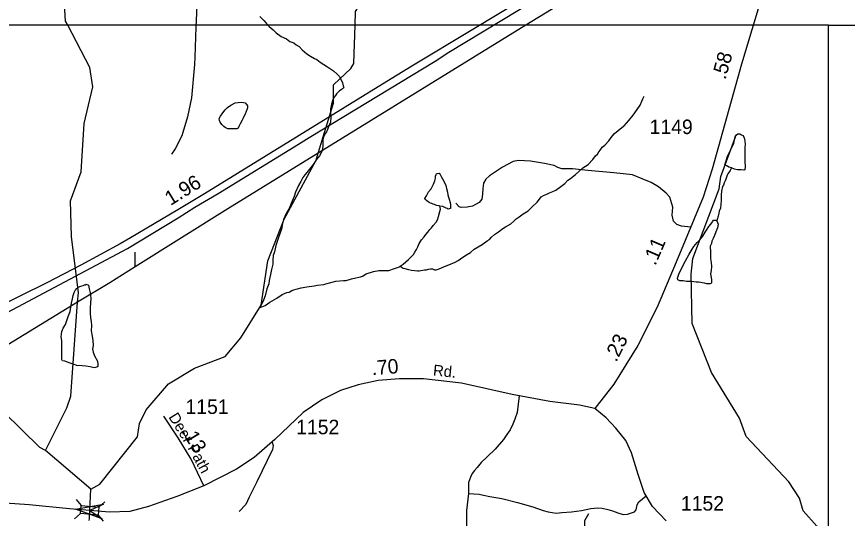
# Model space of a CAD drawing. Extents: x 2001466 to 2224147, y 644118 to 847247.
# Drawn here: x 2022908 to 2030071, y 697641 to 701966 of the extents above; entities that cross this region are included whole.
import ezdxf

# ---------------------------------------------------------------- set-up
doc = ezdxf.new("R2010")
doc.units = 0
for name, color, linetype in [('Exist Hydrographic Creek Single Shore', 7, 'Continuous'), ('Exist Hydrographic Misc Water Feature', 7, 'Continuous'), ('Exist Road Non-System Type 51', 7, 'Continuous'), ('Exist Road Primary US Divided Attributed', 7, 'Continuous'), ('Exist Road Primary US Mileage Hundredths English Label', 7, 'Continuous'), ('Exist Road Secondary Mileage Hundredths English Label', 7, 'Continuous'), ('Exist Road Secondary Structure Standard Bridge Attributed CELL', 7, 'Continuous'), ('Exist Road Secondary Structure Standard Bridge CELL', 7, 'Continuous'), ('Exist Road Secondary Type 41 Attributed', 7, 'Continuous'), ('Exist Road Secondary Type 51 Attributed', 7, 'Continuous'), ('Exist Road Secondary Type 51 Label', 7, 'Continuous'), ('Exist Road Secondary Type 51 Number Label', 7, 'Continuous'), ('Exist Utilities Electrical Transmission Line', 7, 'Continuous'), ('Map Preparation Inset Cut Line', 7, 'Continuous')]:
    doc.layers.add(name, color=color, linetype=linetype)

msp = doc.modelspace()

# ---------------------------------------------------------------- linework, layer by layer
at = {"layer": 'Exist Hydrographic Creek Single Shore'}
msp.add_line((2023549.5, 697893.6), (2023158.5, 698226.4), dxfattribs=at)
for points in [[(2023349.4, 701890.9), (2023330.5, 701927.2), (2023314.5, 702176.9), (2023438.6, 702450), (2023547.7, 702861.2), (2023547.5, 703140.7)], [(2025826.2, 701890.9), (2025830.5, 702010.9), (2025930.6, 702169.6), (2026196.5, 702820.4), (2026202.7, 702966.8)], [(2023434.6, 699504), (2023440.6, 699585.6), (2023382.6, 700069.1), (2023373.6, 700377.7), (2023465.6, 700628.4), (2023489.6, 701044.6), (2023564.5, 701361.4), (2023539.7, 701525.9), (2023349.4, 701890.9)], [(2025789.5, 701519.6), (2025814.5, 701561.7), (2025826.2, 701890.9)], [(2025507.8, 700788.4), (2025639.6, 701220.7), (2025639.6, 701378.2), (2025789.5, 701519.6)], [(2023549.5, 697893.6), (2023624.6, 697934.7), (2023949.6, 698344.8), (2023966.6, 698459.3), (2024024.4, 698576.3), (2024216.5, 698802), (2024440.5, 698935.3), (2024707.4, 699034.9), (2024840.5, 699196.1), (2025015.4, 699478), (2025073.5, 699860.8), (2025214.5, 700218.8), (2025489.5, 700728.4), (2025507.8, 700788.4)], [(2023158.5, 698226.4), (2023341.6, 698593.4), (2023374.6, 698694.5), (2023434.6, 699504)], [(2023534.5, 697623.5), (2023537.4, 697641.1), (2023538.9, 697709.3), (2023549.5, 697893.6)]]:
    msp.add_lwpolyline(points, dxfattribs=at)
at = {"layer": 'Exist Hydrographic Misc Water Feature'}
for points in [[(2025005.2, 701967.4), (2025041.1, 701933.4), (2025061.2, 701909.4), (2025087, 701881.4), (2025121, 701851.5), (2025145, 701825.5), (2025189.1, 701793.5), (2025235.2, 701773.5), (2025265.2, 701751.5), (2025297.2, 701739.5), (2025319.1, 701721.6), (2025343.1, 701707.6), (2025369.1, 701679.6), (2025409.1, 701645.7), (2025441.1, 701625.7), (2025477.2, 701605.7), (2025495.3, 701595.8), (2025525.2, 701573.7), (2025587.3, 701531.8), (2025641.2, 701499.8), (2025675.3, 701465.9), (2025689.2, 701451.9), (2025707.3, 701421.9), (2025717.3, 701395.9), (2025723.3, 701369.9), (2025725.3, 701359.8), (2025729.2, 701355.9)], [(2025705.2, 701335.8), (2025693.3, 701325.6), (2025677.3, 701311.9), (2025667.5, 701299.9), (2025657.4, 701285.9), (2025643.5, 701267.9), (2025633.5, 701247.9), (2025623.4, 701211.8), (2025615.4, 701171.9), (2025615.4, 701133.9), (2025617.5, 701097.8), (2025613.6, 701055.8), (2025601.5, 701029.9), (2025587.5, 700991.9), (2025579.5, 700971.9), (2025571.5, 700961.8), (2025557.6, 700935.8), (2025549.6, 700905.9), (2025547.7, 700879.9), (2025547.7, 700847.9), (2025541.6, 700807.8), (2025519.7, 700765.9), (2025491.8, 700729.9), (2025473.7, 700701.8), (2025443.8, 700663.8), (2025411.8, 700621.8), (2025393.8, 700601.8), (2025375.7, 700579.8), (2025359.7, 700543.8), (2025338, 700509.8), (2025311.9, 700453.7), (2025299.8, 700415.8), (2025275.8, 700353.8), (2025258, 700311.7), (2025232, 700267.7), (2025208, 700217.7), (2025200, 700181.7), (2025192.2, 700133.7), (2025170.2, 700069.7), (2025144.2, 699993.7), (2025132.3, 699937.7), (2025120.2, 699907.7), (2025116.3, 699863.7), (2025118.4, 699831.7), (2025106.3, 699785.7), (2025096.4, 699743.7), (2025086.4, 699691.7), (2025082.5, 699661.7), (2025066.5, 699619.7), (2025050.5, 699557.7), (2025036.6, 699521.7), (2025016.5, 699479.7), (2025004.6, 699457.7)], [(2025729.2, 701355.9), (2025725.3, 701349.8), (2025717.3, 701343.8), (2025711.4, 701339.9), (2025705.2, 701335.8)], [(2026214.2, 699814.4), (2026240.2, 699796.4), (2026256.2, 699794.4), (2026288.2, 699786.4), (2026312.2, 699780.5), (2026342.1, 699776.5), (2026364.1, 699774.5), (2026380.1, 699774.5), (2026426.2, 699784.6), (2026442.2, 699784.6), (2026458.2, 699788.6), (2026476.2, 699790.6), (2026494.1, 699790.6), (2026512.1, 699784.6), (2026524.2, 699784.6), (2026552.1, 699792.6), (2026570.1, 699800.6), (2026584.1, 699806.6), (2026634.1, 699826.7), (2026690.1, 699848.7), (2026715.9, 699862.7), (2026754.1, 699892.7), (2026788.1, 699912.7), (2026820.1, 699932.8), (2026852.1, 699960.8), (2026921.8, 700002.8), (2026963.8, 700032.8), (2026983.9, 700044.8), (2027003.8, 700064.8), (2027027.8, 700086.9), (2027061.8, 700110.9), (2027099.8, 700139), (2027123.8, 700153), (2027167.9, 700178.9), (2027193.7, 700202.9), (2027213.8, 700222.9), (2027239.8, 700239), (2027275.7, 700265), (2027317.5, 700293), (2027353.6, 700325), (2027395.7, 700365.1), (2027415.6, 700393.1), (2027431.6, 700413.1), (2027451.7, 700425.1), (2027479.7, 700435.1), (2027501.7, 700447.2), (2027531.6, 700457.1), (2027557.5, 700471.1), (2027599.5, 700501.1), (2027635.6, 700527.2), (2027661.4, 700555.2), (2027683.6, 700571.2), (2027727.4, 700605.2), (2027783.4, 700657.3), (2027789.4, 700663.3), (2027835.3, 700691.3), (2027875.5, 700733.3), (2027899.5, 700765.3), (2027915.5, 700779.3), (2027929.2, 700801.3), (2027943.4, 700817.3), (2027957.3, 700839.3), (2027979.3, 700857.4), (2028015.3, 700895.3), (2028033.2, 700923.4), (2028045.3, 700939.4), (2028063.1, 700957.4), (2028093.1, 700983.4), (2028141.2, 701021.4), (2028145.1, 701023.4), (2028185.1, 701071.5), (2028223.1, 701115.5), (2028257.1, 701165.4), (2028282.9, 701201.5), (2028299.1, 701237.5), (2028307.1, 701257.5), (2028315.1, 701275.5), (2028319, 701279.5)], [(2024851.6, 701073.4), (2024835.6, 701041.3), (2024823.7, 701019.3), (2024817.8, 701005.4), (2024807.7, 700999.4), (2024793.8, 700997.4), (2024767.7, 700997.4), (2024751.7, 700997.4), (2024729.6, 700997.4), (2024705.6, 701009.3), (2024693.7, 701019.3), (2024677.7, 701035.3), (2024663.8, 701055.3), (2024657.6, 701071.3), (2024655.8, 701087.3), (2024665.6, 701107.3), (2024685.5, 701137.3), (2024705.6, 701161.3), (2024717.5, 701173.3), (2024725.5, 701183.3), (2024755.6, 701203.3), (2024793.6, 701221.3), (2024819.6, 701225.3), (2024843.6, 701227.3), (2024865.5, 701225.4), (2024879.5, 701221.4), (2024893.6, 701205.4), (2024899.6, 701197.4), (2024899.6, 701187.4), (2024899.6, 701179.4), (2024885.6, 701139.4), (2024879.5, 701127.4), (2024857.5, 701083.3), (2024851.6, 701073.4)], [(2029908.9, 697515.7), (2029874.3, 697554.9), (2029807.5, 697572.7), (2029690.4, 697706.3), (2029657.4, 697815.3), (2029565.3, 697954.9), (2029198.5, 698346.2), (2029140.5, 698504.9), (2028898.5, 698897.1), (2028731.4, 699320.4), (2028723.6, 699747.1), (2028739.6, 699881.3), (2028964.5, 700480.4), (2028980.5, 700588.4), (2029105.6, 700930.4)], [(2029071.4, 700662), (2029049.2, 700668), (2029037.3, 700676), (2029029.3, 700680), (2029019.3, 700686), (2029013.3, 700688), (2029025.2, 700722), (2029037.1, 700762.1), (2029057.2, 700802), (2029081.2, 700850), (2029091, 700874.1), (2029099, 700914.1), (2029102.9, 700930), (2029115, 700946), (2029126.9, 700954), (2029142.9, 700954), (2029157.1, 700948), (2029171, 700940), (2029183.1, 700912.1), (2029189.1, 700866.1), (2029185.2, 700838.1), (2029185.2, 700800.1), (2029187.2, 700760.1), (2029185.2, 700710.1), (2029189.1, 700680.1), (2029189.1, 700666.1), (2029187.2, 700652.1), (2029187.2, 700644.1), (2029177.2, 700642.1), (2029155.2, 700644.1), (2029123.2, 700646.1), (2029097.2, 700652.1), (2029071.4, 700662)], [(2026557.8, 700332.6), (2026551.7, 700334.6), (2026527.7, 700336.6), (2026517.8, 700342.5), (2026509.8, 700346.5), (2026499.8, 700348.5), (2026487.7, 700354.5), (2026475.8, 700358.5), (2026463.7, 700364.5), (2026455.7, 700370.5), (2026443.8, 700378.5), (2026437.9, 700384.5), (2026429.9, 700388.5), (2026427.8, 700398.5), (2026441.8, 700420.5), (2026459.8, 700456.4), (2026481.8, 700480.5), (2026501.6, 700520.5), (2026513.7, 700550.5), (2026519.7, 700574.5), (2026519.7, 700590.5), (2026525.6, 700604.5), (2026527.7, 700610.5), (2026533.6, 700614.5), (2026551.7, 700616.5), (2026559.7, 700604.5), (2026567.7, 700586.5), (2026579.6, 700568.5), (2026595.6, 700540.6), (2026607.7, 700510.6), (2026613.6, 700484.6), (2026623.7, 700452.6), (2026625.7, 700428.5), (2026631.9, 700408.6), (2026637.8, 700392.6), (2026645.8, 700364.6), (2026649.7, 700344.6), (2026649.7, 700320.6), (2026649.7, 700312.6), (2026637.8, 700308.6), (2026629.8, 700306.6), (2026621.8, 700310.6), (2026611.8, 700314.6), (2026583.9, 700328.6), (2026557.8, 700332.6)], [(2029071.4, 700662), (2029059.3, 700640.1), (2029041.2, 700610.1), (2029033.2, 700598.1), (2029021.3, 700566), (2029017.2, 700550), (2029009.2, 700534), (2029003.5, 700514.1), (2028993.2, 700502.1), (2028985.4, 700462.1), (2028983.4, 700430), (2028981.3, 700402), (2028983.4, 700378), (2028979.3, 700348.1), (2028975.4, 700316), (2028965.6, 700290), (2028963.5, 700272), (2028957.6, 700246), (2028953.5, 700236.1), (2028951.4, 700226.1), (2028947.5, 700218.1), (2028945.5, 700204.1)], [(2026214.2, 699814.4), (2026240.2, 699832.4), (2026288.2, 699872.4), (2026330, 699916.5), (2026342.1, 699936.5), (2026356.1, 699958.5), (2026366.1, 699980.5), (2026380.1, 700010.5), (2026399.9, 700042.5), (2026421.9, 700068.5), (2026435.8, 700088.5), (2026453.9, 700108.5), (2026471.9, 700130.6), (2026483.8, 700146.5), (2026499.8, 700164.5), (2026525.8, 700192.6), (2026537.9, 700214.6), (2026545.9, 700242.6), (2026555.8, 700286.5), (2026561.7, 700306.5), (2026559.7, 700320.6), (2026557.8, 700332.6)], [(2028747.8, 699680.1), (2028729.9, 699682), (2028683.8, 699683.9), (2028655.9, 699687.9), (2028641.8, 699688), (2028625.8, 699687.9), (2028619.8, 699689.9), (2028609.8, 699697.9), (2028605.9, 699711.9), (2028617.8, 699745.9), (2028639.7, 699795.9), (2028675.8, 699861.9), (2028705.8, 699917.9), (2028733.8, 699961.9), (2028747.6, 699983.9), (2028775.7, 700018), (2028799.7, 700042), (2028825.7, 700072), (2028843.5, 700108), (2028861.6, 700134), (2028875.5, 700156), (2028893.6, 700178), (2028907.5, 700198.1), (2028911.4, 700204), (2028917.6, 700210.1), (2028921.5, 700212.1), (2028937.5, 700212.1), (2028945.5, 700204.1)], [(2028945.5, 700204.1), (2028955.5, 700178), (2028951.4, 700146), (2028937.7, 700110), (2028925.6, 700078.1), (2028913.7, 700052.1), (2028901.6, 700030), (2028897.7, 700010), (2028887.6, 699988), (2028891.5, 699932.1), (2028891.7, 699882), (2028895.8, 699846.1), (2028897.7, 699812.1), (2028895.8, 699776.1), (2028891.7, 699748.1), (2028895.8, 699718.1), (2028897.7, 699698.1), (2028899.7, 699688.1), (2028899.9, 699676.1), (2028897.9, 699672.1), (2028893.8, 699664.1), (2028883.9, 699662.1), (2028871.8, 699662.1), (2028857.9, 699662.1), (2028837.8, 699668.1), (2028817.9, 699672.1), (2028805.8, 699674.1), (2028785.9, 699676.1), (2028777.9, 699676.1), (2028765.8, 699676), (2028747.8, 699680.1)], [(2025004.6, 699457.7), (2025008.5, 699457.7), (2025022.6, 699463.7), (2025052.5, 699475.7), (2025092.5, 699503.7), (2025152.6, 699537.8), (2025198.3, 699571.8), (2025238.3, 699587.8), (2025258.4, 699591.8), (2025282.4, 699603.9), (2025298.4, 699611.9), (2025318.3, 699617.9), (2025360.3, 699627.9), (2025410.4, 699635.9), (2025474.3, 699646), (2025502.4, 699652), (2025558.2, 699658.1), (2025574.2, 699662.1), (2025660.3, 699684.1), (2025726.3, 699692.1), (2025748.3, 699692.1), (2025796.3, 699704.2), (2025832.4, 699714.2), (2025858.2, 699720.2), (2025872.3, 699724.2), (2025890.2, 699728.2), (2025922.2, 699748.2), (2025984.3, 699768.2), (2026032.1, 699776.3), (2026066.1, 699778.3), (2026106.1, 699778.4), (2026116.1, 699776.4), (2026166.2, 699794.4), (2026208.2, 699810.4), (2026214.2, 699814.4)], [(2023420.9, 698960.8), (2023401.1, 698966.7), (2023370.9, 698978.8), (2023322.9, 698994.7), (2023303, 698998.7), (2023298.9, 699010.7), (2023298.9, 699066.7), (2023298.9, 699128.7), (2023296.9, 699174.7), (2023293, 699206.7), (2023296.9, 699250.7), (2023309, 699280.7), (2023328.9, 699310.7), (2023352.9, 699380.7), (2023370.7, 699424.7), (2023382.8, 699496.7), (2023388.8, 699532.7), (2023396.7, 699560.7), (2023404.7, 699588.7), (2023418.7, 699616.7), (2023438.6, 699632.7), (2023460.7, 699642.7), (2023482.7, 699648.7), (2023492.7, 699652.7), (2023498.7, 699652.7), (2023508.7, 699658.8)], [(2023508.7, 699658.8), (2023526.8, 699650.7), (2023534.7, 699618.7), (2023542.7, 699584.8), (2023548.7, 699538.8), (2023544.6, 699494.8), (2023542.7, 699458.7), (2023542.7, 699408.8), (2023544.8, 699370.8), (2023550.7, 699338.8), (2023552.8, 699302.8), (2023550.9, 699256.8), (2023558.9, 699210.8), (2023564.9, 699172.8), (2023566.9, 699130.9), (2023562.8, 699098.9), (2023566.9, 699072.9), (2023579, 699042.9), (2023605.1, 698994.9), (2023609, 698968.9), (2023609, 698950.9), (2023601, 698942.9), (2023577, 698938.9), (2023543, 698946.9), (2023505, 698952.9), (2023473, 698956.8), (2023425, 698958.7), (2023420.9, 698960.8)], [(2023158.5, 698226.4), (2023108.4, 698250.4), (2022641.5, 698709.4), (2022422.9, 698888.1)], [(2027897.6, 696823.8), (2027891.5, 696955.5), (2027799.4, 697095.2), (2027807.4, 697623.2), (2027841.5, 697681.6)]]:
    msp.add_lwpolyline(points, dxfattribs=at)
at = {"layer": 'Exist Road Non-System Type 51'}
msp.add_line((2023930.2, 699809.3), (2023931.7, 699934.1), dxfattribs=at)
for points in [[(2024444.6, 701617.4), (2024442.2, 701551.6), (2024415.4, 701266.6), (2024382.7, 701102.9), (2024331.7, 700936.9), (2024275.8, 700826.7), (2024243, 700780.6)], [(2028719.8, 700151.2), (2028641.3, 700159.1), (2028599.7, 700175.1), (2028570.9, 700203.9), (2028561.3, 700255.1), (2028564.5, 700322.3), (2028539, 700408.6), (2028507, 700443.8), (2028443, 700498.2), (2028379.1, 700536.6), (2028302.3, 700568.6), (2028219.2, 700600.6), (2028056.1, 700619.8), (2027832.3, 700639), (2027701.2, 700655), (2027608.4, 700655), (2027573.3, 700664.6), (2027541.3, 700683.7), (2027458.1, 700699.7), (2027339.8, 700718.9), (2027234.3, 700725.3), (2027189.5, 700715.7), (2027096.8, 700667.8), (2026984.9, 700594.2), (2026952.9, 700565.4), (2026933.7, 700530.2), (2026927.3, 700485.4), (2026924.1, 700434.2), (2026917.7, 700392.6), (2026895.4, 700363.8), (2026869.8, 700347.9), (2026837.8, 700331.9), (2026793, 700322.3), (2026741.9, 700319.1), (2026722.7, 700325.5), (2026693.9, 700357.4)], [(2027241.1, 698698.2), (2027222.6, 698554.7), (2027203.4, 698497.3), (2027186.7, 698452.8), (2027164.7, 698402.7), (2027134.5, 698364.5), (2027105, 698320.5), (2027035.3, 698237.7), (2026964.8, 698172.7), (2026914.7, 698122.7), (2026878.7, 698080.7), (2026856.7, 698052.7), (2026836.8, 698026.7), (2026820.7, 697994.7), (2026804.8, 697950.6), (2026802.9, 697856.6)], [(2025110.2, 698298.9), (2025120.5, 698267.9), (2025114.1, 698235.7), (2024978.9, 697957.2), (2024912.9, 697823.5), (2024885.6, 697759.1), (2024827.7, 697699.5)], [(2026802.9, 697856.6), (2026786.9, 697708.5), (2026786.9, 697560.7)], [(2026802.9, 697856.6), (2026894.7, 697848.7), (2026934.8, 697840.7), (2026988.7, 697828.6), (2027090.8, 697812.7), (2027226.7, 697778.8), (2027358.8, 697740.9), (2027448.9, 697708.8), (2027490.9, 697697), (2027524.8, 697690.9), (2027562.9, 697684.9), (2027608.8, 697691), (2027690.9, 697697.1), (2027778.8, 697709.1), (2027858.9, 697725.1), (2027917.2, 697731.7), (2027957.4, 697729.5), (2028004.7, 697717.1), (2028046.7, 697707.3), (2028090.8, 697689.2), (2028137.9, 697675.6), (2028174.7, 697677.3), (2028210.8, 697689.3), (2028234.8, 697697.2), (2028250.7, 697715.3), (2028258.8, 697757.4), (2028272.5, 697783.5), (2028336.5, 697835.5)]]:
    msp.add_lwpolyline(points, dxfattribs=at)
at = {"layer": 'Exist Road Primary US Divided Attributed'}
for points in [[(2029594.3, 703535.4), (2029470.7, 703458.2), (2028875.7, 703094.4), (2028744.5, 703014.5), (2028584.6, 702916.2), (2027863, 702478.6), (2027674.7, 702363), (2027348.5, 702163.1), (2026826.3, 701846.7), (2026331, 701548), (2026138.2, 701428.1), (2025345.1, 700942), (2024527, 700439.3), (2024299.1, 700299.1), (2023889.6, 700058.2), (2023801.5, 700007), (2023463.1, 699824.5), (2023169.6, 699672.1), (2022239.9, 699214.9), (2021326.9, 698766.1)], [(2021478.6, 698762.7), (2021601.9, 698818.7), (2022060, 699049), (2022644.6, 699321.5), (2023865.5, 699967.6), (2024300.3, 700232.4), (2024445.7, 700324), (2024644.7, 700441.7), (2025337.6, 700865.2), (2025429.3, 700924.6), (2026516.5, 701580.8), (2026634.6, 701659.9), (2027380.7, 702113.6), (2027700.2, 702307.1), (2028342.2, 702702.5), (2028570.3, 702839.6), (2028768.1, 702960.7), (2029256.1, 703260.4), (2029519.5, 703418.8), (2029577.8, 703456.8)]]:
    msp.add_lwpolyline(points, dxfattribs=at)
at = {"layer": 'Exist Road Secondary Structure Standard Bridge Attributed CELL'}
msp.add_lwpolyline([(2023647, 697637), (2023417.4, 697719.3), (2023657.3, 697762.8), (2023538.9, 697709.3)], close=True, dxfattribs=at)
at = {"layer": 'Exist Road Secondary Structure Standard Bridge CELL'}
for p, q in [((2023421.7, 697804.8), (2023466, 697751.9)), ((2023616.5, 697738.3), (2023669.4, 697782.6)), ((2023406.9, 697637.3), (2023459.8, 697681.6)), ((2023610.4, 697669.6), (2023654.7, 697616.7))]:
    msp.add_line(p, q, dxfattribs=at)
msp.add_lwpolyline([(2023466, 697751.9), (2023616.5, 697738.6), (2023610.3, 697668.3), (2023459.8, 697681.6)], close=True, dxfattribs=at)
at = {"layer": 'Exist Road Secondary Type 41 Attributed'}
msp.add_lwpolyline([(2024523.2, 697920.7), (2024411.8, 698152), (2024302, 698335.8), (2024177.5, 698521.7)], dxfattribs=at)
at = {"layer": 'Exist Road Secondary Type 51 Attributed'}
for points in [[(2029509.4, 703114.8), (2029392.2, 702618.3), (2029360.6, 702394.3), (2029335.2, 702151.4), (2029158.9, 701555.6), (2028904.5, 700651.3), (2028826.4, 700408.4), (2028595.2, 699850.6), (2028430.6, 699461.9), (2028262.7, 699130.2), (2028055.8, 698796.4), (2027892.2, 698589.3)], [(2024464.1, 702121.5), (2024454.1, 701874.9), (2024444.6, 701617.4)], [(2027892.2, 698589.3), (2027761.3, 698616.8), (2027505.8, 698648.5), (2027179.7, 698709.8), (2026742.6, 698807), (2026415.4, 698842.9), (2026208.5, 698843.9), (2026025.9, 698829.1), (2025853.8, 698793.2), (2025701.8, 698743.6), (2025539.7, 698662.2), (2025379.3, 698552.4), (2025134.4, 698320), (2024957, 698165.8), (2024802.9, 698064.3), (2024523.2, 697920.7)], [(2028507.6, 697620.7), (2028391.5, 697743.2), (2028319.7, 697863.6), (2028265.9, 698017.9), (2028208.9, 698205.9), (2028160.3, 698311.5), (2028073.8, 698419.3), (2027991.4, 698508), (2027892.2, 698589.3)], [(2024523.2, 697920.7), (2024288.8, 697829.8), (2024046, 697743.2), (2023885.6, 697701), (2023710.4, 697693.6), (2023538.9, 697709.3)], [(2023538.9, 697709.3), (2023365.7, 697724.2), (2023017.3, 697758), (2022810.4, 697770.7), (2022643.7, 697751.7), (2022314.3, 697739), (2021933.2, 697743.2), (2021530, 697753.8), (2021006.4, 697796), (2020772.6, 697806.6)]]:
    msp.add_lwpolyline(points, dxfattribs=at)
at = {"layer": 'Exist Utilities Electrical Transmission Line'}
for p, q in [((2028412.5, 702578.2), (2027297.2, 701890.9)), ((2027297.2, 701890.9), (2025507.8, 700788.4)), ((2023434.6, 699504), (2022422.9, 698888.1))]:
    msp.add_line(p, q, dxfattribs=at)
for points in [[(2025507.8, 700788.4), (2024729.6, 700308.9), (2023930.2, 699809.3)], [(2023930.2, 699809.3), (2023711.1, 699672.3), (2023434.6, 699504)]]:
    msp.add_lwpolyline(points, dxfattribs=at)
at = {"layer": 'Map Preparation Inset Cut Line'}
for p, q in [((2023349.4, 701890.9), (2021830, 701890.9)), ((2024416.4, 701890.9), (2023349.4, 701890.9)), ((2025826.2, 701890.9), (2024416.4, 701890.9)), ((2026833, 701890.9), (2025826.2, 701890.9)), ((2027297.2, 701890.9), (2026833, 701890.9)), ((2029217.4, 701890.9), (2027297.2, 701890.9)), ((2029908.9, 701890.9), (2029217.4, 701890.9)), ((2029908.9, 701890.9), (2030404.6, 701890.9)), ((2029908.9, 697515.7), (2029908.9, 701890.9))]:
    msp.add_line(p, q, dxfattribs=at)

# ---------------------------------------------------------------- texts
at = {"layer": 'Exist Road Primary US Mileage Hundredths English Label'}
msp.add_text('1.96', height=125, rotation=31.60562, dxfattribs=at).set_placement((2024234.7, 700332.8))
at = {"layer": 'Exist Road Secondary Mileage Hundredths English Label'}
for s, rotation, p in [('.58', 74.2862, (2029018.9, 701416.9)), ('.11', 66.7248, (2028415.3, 699813.7)), ('.23', 63.2934, (2028078.2, 698981.7)), ('.70', 4.62958, (2025973.1, 698874.2)), ('.13', 300.84939, (2024327.1, 698389.8))]:
    msp.add_text(s, height=125, rotation=rotation, dxfattribs=at).set_placement(p)
at = {"layer": 'Exist Road Secondary Type 51 Label'}
for s, rotation, p in [('Rd.', 354.39143, (2026495.3, 698872.2)), ('Deer', 301.89213, (2024214.6, 698514.7)), ('Path', 298.46328, (2024380.2, 698249))]:
    msp.add_text(s, height=95, rotation=rotation, dxfattribs=at).set_placement(p)
at = {"layer": 'Exist Road Secondary Type 51 Number Label'}
for s, p in [('1149', (2028365.3, 700953.4)), ('1151', (2024364.2, 698541.2)), ('1152', (2025318.5, 698366)), ('1152', (2028635.4, 697707.6))]:
    msp.add_text(s, height=125, dxfattribs=at).set_placement(p)

doc.saveas('drawing.dxf')
